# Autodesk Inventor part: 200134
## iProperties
Created: 2007-10
Part Number: 200134
Document SubType Name: Modeling
Designer: TH
Density: 7.85 g/cm^3
Mass: 90.2441 g
Surface Area: 99.9897 cm^2
Volume: 11.4961 cm^3
Material: Steel
Description: CORNER BRACKET
Component Category: Lower Component
Author: TH
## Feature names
1. Extrusion1
2. Fillet1
3. Shell1
4. Extrusion2
5. Extrusion3
6. Hole1
7. Hole2
8. Extrusion4
9. Fillet3
